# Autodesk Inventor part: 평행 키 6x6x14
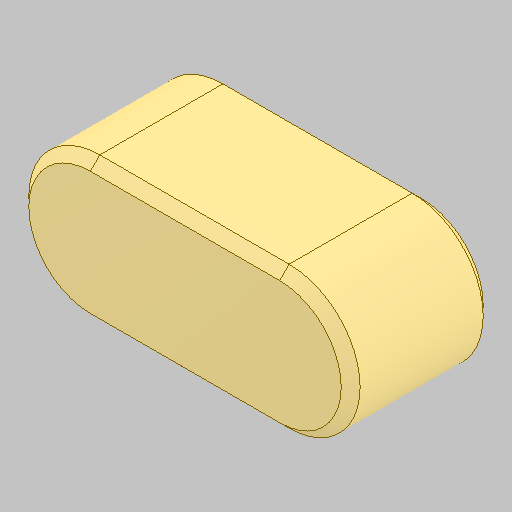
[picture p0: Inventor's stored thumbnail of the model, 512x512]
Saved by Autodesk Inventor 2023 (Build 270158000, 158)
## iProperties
Created: 2025-09
Part Number: 평행 키 6x6x14
Material: 강철, 연강
Description: 키 및 해당 키홈
Document SubType Name: Modeling
Designer: home
Density: 7.85 g/cm^3
Appearance: 기본값
Author: jhkim
Sending System: Autodesk Inventor 2026
Preprocessor: ST-DEVELOPER v20.1
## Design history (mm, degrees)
feature "Solid1"
node "솔리드1"
